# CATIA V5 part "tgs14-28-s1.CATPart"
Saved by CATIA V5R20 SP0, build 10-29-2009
Part number: TGS14-28-S1
Revision: 1
Definition: design
Nomenclature: TGS14-28-S1
Source: made
Description: NOT SPECIFIED
Bounding box of the stored display mesh (mm): x -22 to 0.8, y 0 to 14, z -6 to 6
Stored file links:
  C:\Users\Raffaele\Desktop\3D X SITO CF\I-MOLD\TGS-S1\tgs14-s1.step\tgs14-28-s1.CATPart
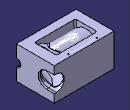
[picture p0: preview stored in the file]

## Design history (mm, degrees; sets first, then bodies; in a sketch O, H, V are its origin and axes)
Set1
  Line1 "LINE #4030": stored without definition
  DatumCurve1 "COMPOSITE_CURVE #4083"
  DatumCurve2 "COMPOSITE_CURVE #4134"
  DatumCurve3 "COMPOSITE_CURVE #4213"
  DatumCurve4 "COMPOSITE_CURVE #4256"
  DatumCurve5 "COMPOSITE_CURVE #4485"
  DatumCurve6 "COMPOSITE_CURVE #4626"
  DatumCurve7 "COMPOSITE_CURVE #4653"
  DatumCurve8 "COMPOSITE_CURVE #4711"
  DatumCurve9 "COMPOSITE_CURVE #4766"
  DatumCurve10 "COMPOSITE_CURVE #4795"
  DatumSurface1 "OPEN_SHELL #4020"
Body1 "MANIFOLD_SOLID_BREP #4021" (main body)
  Solid1: solid without history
